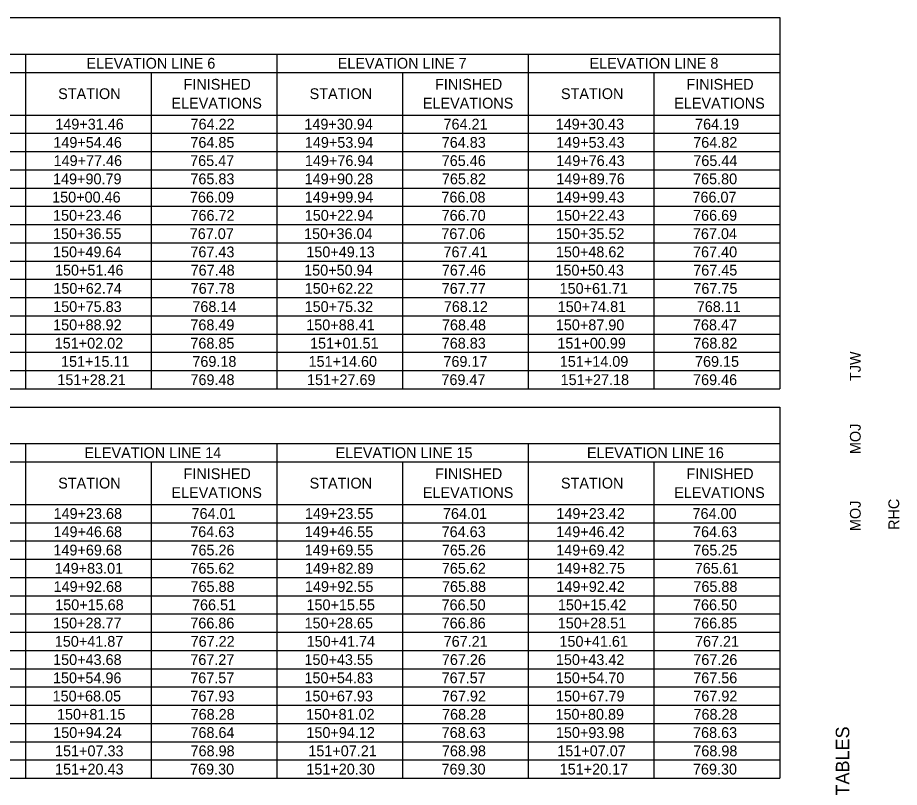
# Model space of a CAD drawing. Extents: x 2.7 to 33.4, y 1.1 to 21.
# Drawn here: x 21.94 to 33.41, y 11 to 21 of the extents above; entities that cross this region are included whole.
import ezdxf

# ---------------------------------------------------------------- set-up
doc = ezdxf.new("R2010")
doc.units = 0
doc.layers.add('BR_X_Beam_Object', color=7, linetype='Continuous')
doc.layers.add('BR_X_Slab_Object', color=7, linetype='Continuous')

msp = doc.modelspace()

# ---------------------------------------------------------------- linework, layer by layer
at = {"layer": 'BR_X_Slab_Object'}
for p, q in [((12.243, 21), (22.046, 21)), ((22.046, 21), (28.582, 21)), ((28.582, 21), (31.85, 21)), ((31.85, 21), (31.85, 19.735)), ((12.243, 20.526), (22.046, 20.526)), ((22.046, 20.526), (28.582, 20.526)), ((22.046, 20.526), (22.046, 19.735)), ((25.314, 20.526), (25.314, 19.735)), ((28.582, 20.526), (31.85, 20.526)), ((28.582, 20.526), (28.582, 19.735)), ((12.243, 20.288), (22.046, 20.288)), ((22.046, 20.288), (28.582, 20.288)), ((23.68, 20.288), (23.68, 19.735)), ((26.948, 20.288), (26.948, 19.735)), ((28.582, 20.288), (31.85, 20.288)), ((30.216, 20.288), (30.216, 19.735)), ((12.243, 19.735), (22.046, 19.735)), ((22.046, 19.735), (28.582, 19.735)), ((22.046, 19.735), (22.046, 18.549)), ((23.68, 19.735), (23.68, 18.549)), ((25.314, 19.735), (25.314, 18.549)), ((26.948, 19.735), (26.948, 18.549)), ((28.582, 19.735), (31.85, 19.735)), ((28.582, 19.735), (28.582, 18.549)), ((30.216, 19.735), (30.216, 18.549)), ((31.85, 19.735), (31.85, 18.549)), ((12.243, 19.498), (22.046, 19.498)), ((22.046, 19.498), (28.582, 19.498)), ((28.582, 19.498), (31.85, 19.498)), ((12.243, 19.261), (22.046, 19.261)), ((22.046, 19.261), (28.582, 19.261)), ((28.582, 19.261), (31.85, 19.261)), ((12.243, 19.024), (22.046, 19.024)), ((22.046, 19.024), (28.582, 19.024)), ((28.582, 19.024), (31.85, 19.024)), ((12.243, 18.786), (22.046, 18.786)), ((22.046, 18.786), (28.582, 18.786)), ((28.582, 18.786), (31.85, 18.786)), ((12.243, 18.549), (22.046, 18.549)), ((22.046, 18.549), (28.582, 18.549)), ((22.046, 18.549), (22.046, 18.312)), ((23.68, 18.549), (23.68, 18.312)), ((25.314, 18.549), (25.314, 18.312)), ((26.948, 18.549), (26.948, 18.312)), ((28.582, 18.549), (31.85, 18.549)), ((28.582, 18.549), (28.582, 18.312)), ((30.216, 18.549), (30.216, 18.312)), ((31.85, 18.549), (31.85, 18.312)), ((12.243, 18.312), (22.046, 18.312)), ((22.046, 18.312), (28.582, 18.312)), ((22.046, 18.312), (22.046, 17.6)), ((23.68, 18.312), (23.68, 17.6)), ((25.314, 18.312), (25.314, 17.6)), ((26.948, 18.312), (26.948, 17.6)), ((28.582, 18.312), (31.85, 18.312)), ((28.582, 18.312), (28.582, 17.6)), ((30.216, 18.312), (30.216, 17.6)), ((31.85, 18.312), (31.85, 17.6)), ((12.243, 18.075), (22.046, 18.075)), ((22.046, 18.075), (28.582, 18.075)), ((28.582, 18.075), (31.85, 18.075)), ((12.243, 17.838), (22.046, 17.838)), ((22.046, 17.838), (28.582, 17.838)), ((28.582, 17.838), (31.85, 17.838)), ((12.243, 17.6), (22.046, 17.6)), ((22.046, 17.6), (28.582, 17.6)), ((22.046, 17.6), (22.046, 17.126)), ((23.68, 17.6), (23.68, 17.126)), ((25.314, 17.6), (25.314, 17.126)), ((26.948, 17.6), (26.948, 17.126)), ((28.582, 17.6), (31.85, 17.6)), ((28.582, 17.6), (28.582, 17.126)), ((30.216, 17.6), (30.216, 17.126)), ((31.85, 17.6), (31.85, 17.126)), ((12.243, 17.363), (22.046, 17.363)), ((22.046, 17.363), (28.582, 17.363)), ((28.582, 17.363), (31.85, 17.363)), ((12.243, 17.126), (22.046, 17.126)), ((22.046, 17.126), (28.582, 17.126)), ((22.046, 17.126), (22.046, 16.415)), ((23.68, 17.126), (23.68, 16.415)), ((25.314, 17.126), (25.314, 16.415)), ((26.948, 17.126), (26.948, 16.415)), ((28.582, 17.126), (31.85, 17.126)), ((28.582, 17.126), (28.582, 16.415)), ((30.216, 17.126), (30.216, 16.415)), ((31.85, 17.126), (31.85, 16.415)), ((12.243, 16.889), (22.046, 16.889)), ((22.046, 16.889), (28.582, 16.889)), ((28.582, 16.889), (31.85, 16.889)), ((12.243, 16.652), (22.046, 16.652)), ((22.046, 16.652), (28.582, 16.652)), ((28.582, 16.652), (31.85, 16.652)), ((12.243, 16.415), (22.046, 16.415)), ((22.046, 16.415), (28.582, 16.415)), ((22.046, 16.415), (22.046, 16.177)), ((23.68, 16.415), (23.68, 16.177)), ((25.314, 16.415), (25.314, 16.177)), ((26.948, 16.415), (26.948, 16.177)), ((28.582, 16.415), (31.85, 16.415)), ((28.582, 16.415), (28.582, 16.177)), ((30.216, 16.415), (30.216, 16.177)), ((31.85, 16.415), (31.85, 16.177)), ((12.243, 16.177), (22.046, 16.177)), ((22.046, 16.177), (28.582, 16.177)), ((28.582, 16.177), (31.85, 16.177)), ((12.243, 15.94), (22.046, 15.94)), ((22.046, 15.94), (28.582, 15.94)), ((28.582, 15.94), (31.85, 15.94)), ((31.85, 15.94), (31.85, 14.952)), ((12.243, 15.466), (22.046, 15.466)), ((22.046, 15.466), (28.582, 15.466)), ((22.046, 15.466), (22.046, 14.952)), ((25.314, 15.466), (25.314, 14.952)), ((28.582, 15.466), (31.85, 15.466)), ((28.582, 15.466), (28.582, 14.952)), ((12.243, 15.229), (22.046, 15.229)), ((22.046, 15.229), (28.582, 15.229)), ((23.68, 15.229), (23.68, 14.952)), ((26.948, 15.229), (26.948, 14.952)), ((28.582, 15.229), (31.85, 15.229)), ((30.216, 15.229), (30.216, 14.952)), ((22.046, 14.952), (22.046, 14.201)), ((23.68, 14.952), (23.68, 14.201)), ((25.314, 14.952), (25.314, 14.201)), ((26.948, 14.952), (26.948, 14.201)), ((28.582, 14.952), (28.582, 14.201)), ((30.216, 14.952), (30.216, 14.201)), ((31.85, 14.952), (31.85, 14.201)), ((12.243, 14.675), (22.046, 14.675)), ((22.046, 14.675), (28.582, 14.675)), ((28.582, 14.675), (31.85, 14.675)), ((12.243, 14.438), (22.046, 14.438)), ((22.046, 14.438), (28.582, 14.438)), ((28.582, 14.438), (31.85, 14.438)), ((12.243, 14.201), (22.046, 14.201)), ((22.046, 14.201), (28.582, 14.201)), ((22.046, 14.201), (22.046, 13.015)), ((23.68, 14.201), (23.68, 13.015)), ((25.314, 14.201), (25.314, 13.015)), ((26.948, 14.201), (26.948, 13.015)), ((28.582, 14.201), (31.85, 14.201)), ((28.582, 14.201), (28.582, 13.015)), ((30.216, 14.201), (30.216, 13.015)), ((31.85, 14.201), (31.85, 13.015)), ((12.243, 13.964), (22.046, 13.964)), ((22.046, 13.964), (28.582, 13.964)), ((28.582, 13.964), (31.85, 13.964)), ((12.243, 13.727), (22.046, 13.727)), ((22.046, 13.727), (28.582, 13.727)), ((28.582, 13.727), (31.85, 13.727)), ((12.243, 13.489), (22.046, 13.489)), ((22.046, 13.489), (28.582, 13.489)), ((28.582, 13.489), (31.85, 13.489)), ((12.243, 13.252), (22.046, 13.252)), ((22.046, 13.252), (28.582, 13.252)), ((28.582, 13.252), (31.85, 13.252)), ((12.243, 13.015), (22.046, 13.015)), ((22.046, 13.015), (28.582, 13.015)), ((22.046, 13.015), (22.046, 11.829)), ((23.68, 13.015), (23.68, 11.829)), ((25.314, 13.015), (25.314, 11.829)), ((26.948, 13.015), (26.948, 11.829)), ((28.582, 13.015), (31.85, 13.015)), ((28.582, 13.015), (28.582, 11.829)), ((30.216, 13.015), (30.216, 11.829)), ((31.85, 13.015), (31.85, 11.829)), ((12.243, 12.778), (22.046, 12.778)), ((22.046, 12.778), (28.582, 12.778)), ((28.582, 12.778), (31.85, 12.778)), ((12.243, 12.541), (22.046, 12.541)), ((22.046, 12.541), (28.582, 12.541)), ((28.582, 12.541), (31.85, 12.541)), ((12.243, 12.304), (22.046, 12.304)), ((22.046, 12.304), (28.582, 12.304)), ((28.582, 12.304), (31.85, 12.304)), ((12.243, 12.066), (22.046, 12.066)), ((22.046, 12.066), (28.582, 12.066)), ((28.582, 12.066), (31.85, 12.066)), ((12.243, 11.829), (22.046, 11.829)), ((22.046, 11.829), (28.582, 11.829)), ((22.046, 11.829), (22.046, 11.118)), ((23.68, 11.829), (23.68, 11.118)), ((25.314, 11.829), (25.314, 11.118)), ((26.948, 11.829), (26.948, 11.118)), ((28.582, 11.829), (31.85, 11.829)), ((28.582, 11.829), (28.582, 11.118)), ((30.216, 11.829), (30.216, 11.118)), ((31.85, 11.829), (31.85, 11.118)), ((12.243, 11.592), (22.046, 11.592)), ((22.046, 11.592), (28.582, 11.592)), ((28.582, 11.592), (31.85, 11.592)), ((12.243, 11.355), (22.046, 11.355)), ((22.046, 11.355), (28.582, 11.355)), ((28.582, 11.355), (31.85, 11.355)), ((12.243, 11.118), (22.046, 11.118)), ((22.046, 11.118), (28.582, 11.118)), ((28.582, 11.118), (31.85, 11.118))]:
    msp.add_line(p, q, dxfattribs=at)

# ---------------------------------------------------------------- texts
at = {"layer": 'BR_X_Beam_Object'}
for s, p in [('ELEVATION LINE 6', (22.839, 20.337)), ('ELEVATION LINE 7', (26.105, 20.337)), ('ELEVATION LINE 8', (29.378, 20.337)), ('FINISHED', (24.102, 20.064)), ('FINISHED', (27.37, 20.064)), ('FINISHED', (30.637, 20.064)), ('STATION', (22.472, 19.942)), ('STATION', (25.74, 19.942)), ('STATION', (29.007, 19.942)), ('ELEVATIONS', (23.944, 19.819)), ('ELEVATIONS', (27.212, 19.819)), ('ELEVATIONS', (30.48, 19.819)), ('149+31.46', (22.434, 19.546)), ('764.22', (24.192, 19.546)), ('149+30.94', (25.672, 19.546)), ('764.21', (27.48, 19.546)), ('149+30.43', (28.938, 19.546)), ('764.19', (30.75, 19.546)), ('149+54.46', (22.409, 19.309)), ('764.85', (24.19, 19.309)), ('149+53.94', (25.678, 19.309)), ('764.83', (27.457, 19.309)), ('149+53.43', (28.944, 19.309)), ('764.82', (30.726, 19.309)), ('149+77.46', (22.412, 19.072)), ('765.47', (24.187, 19.072)), ('149+76.94', (25.679, 19.072)), ('765.46', (27.457, 19.072)), ('149+76.43', (28.945, 19.072)), ('765.44', (30.727, 19.072)), ('149+90.79', (22.405, 18.835)), ('765.83', (24.19, 18.835)), ('149+90.28', (25.675, 18.835)), ('765.82', (27.459, 18.835)), ('149+89.76', (28.946, 18.835)), ('765.80', (30.724, 18.835)), ('150+00.46', (22.393, 18.598)), ('766.09', (24.184, 18.598)), ('149+99.94', (25.677, 18.598)), ('766.08', (27.453, 18.598)), ('149+99.43', (28.943, 18.598)), ('766.07', (30.716, 18.598)), ('150+23.46', (22.405, 18.361)), ('766.72', (24.191, 18.361)), ('150+22.94', (25.677, 18.361)), ('766.70', (27.456, 18.361)), ('150+22.43', (28.943, 18.361)), ('766.69', (30.724, 18.361)), ('150+36.55', (22.404, 18.123)), ('767.07', (24.182, 18.123)), ('150+36.04', (25.668, 18.123)), ('767.06', (27.452, 18.123)), ('150+35.52', (28.942, 18.123)), ('767.04', (30.722, 18.123)), ('150+49.64', (22.405, 17.886)), ('767.43', (24.19, 17.886)), ('150+49.13', (25.697, 17.886)), ('767.41', (27.48, 17.886)), ('150+48.62', (28.941, 17.886)), ('767.40', (30.724, 17.886)), ('150+51.46', (22.43, 17.649)), ('767.48', (24.193, 17.649)), ('150+50.94', (25.669, 17.649)), ('767.46', (27.458, 17.649)), ('150+50.43', (28.935, 17.649)), ('767.45', (30.726, 17.649)), ('150+62.74', (22.409, 17.412)), ('767.78', (24.194, 17.412)), ('150+62.22', (25.676, 17.412)), ('767.77', (27.457, 17.412)), ('150+61.71', (28.989, 17.412)), ('767.75', (30.728, 17.412)), ('150+75.83', (22.407, 17.175)), ('768.14', (24.216, 17.175)), ('150+75.32', (25.675, 17.175)), ('768.12', (27.484, 17.175)), ('150+74.81', (28.964, 17.175)), ('768.11', (30.772, 17.175)), ('150+88.92', (22.406, 16.938)), ('768.49', (24.19, 16.938)), ('150+88.41', (25.696, 16.938)), ('768.48', (27.46, 16.938)), ('150+87.90', (28.94, 16.938)), ('768.47', (30.722, 16.938)), ('151+02.02', (22.427, 16.7)), ('768.85', (24.19, 16.7)), ('151+01.51', (25.746, 16.7)), ('768.83', (27.457, 16.7)), ('151+00.99', (28.96, 16.7)), ('768.82', (30.727, 16.7)), ('151+15.11', (22.509, 16.463)), ('769.18', (24.216, 16.463)), ('151+14.60', (25.726, 16.463)), ('769.17', (27.479, 16.463)), ('151+14.09', (28.992, 16.463)), ('769.15', (30.749, 16.463)), ('151+28.21', (22.461, 16.226)), ('769.48', (24.191, 16.226)), ('151+27.69', (25.706, 16.226)), ('769.47', (27.453, 16.226)), ('151+27.18', (29.002, 16.226)), ('769.46', (30.724, 16.226)), ('ELEVATION LINE 14', (22.812, 15.277)), ('ELEVATION LINE 15', (26.078, 15.277)), ('ELEVATION LINE 16', (29.345, 15.277)), ('FINISHED', (24.102, 15.004)), ('FINISHED', (27.37, 15.004)), ('FINISHED', (30.637, 15.004)), ('STATION', (22.472, 14.882)), ('STATION', (25.74, 14.882)), ('STATION', (29.007, 14.882)), ('ELEVATIONS', (23.944, 14.759)), ('ELEVATIONS', (27.212, 14.759)), ('ELEVATIONS', (30.48, 14.759)), ('149+23.68', (22.412, 14.487)), ('764.01', (24.205, 14.487)), ('149+23.55', (25.679, 14.487)), ('764.01', (27.473, 14.487)), ('149+23.42', (28.947, 14.487)), ('764.00', (30.717, 14.487)), ('149+46.68', (22.411, 14.25)), ('764.63', (24.188, 14.25)), ('149+46.55', (25.677, 14.25)), ('764.63', (27.456, 14.25)), ('149+46.42', (28.945, 14.25)), ('764.63', (30.724, 14.25)), ('149+69.68', (22.41, 14.012)), ('765.26', (24.191, 14.012)), ('149+69.55', (25.677, 14.012)), ('765.26', (27.458, 14.012)), ('149+69.42', (28.945, 14.012)), ('765.25', (30.727, 14.012)), ('149+83.01', (22.426, 13.775)), ('765.62', (24.19, 13.775)), ('149+82.89', (25.68, 13.775)), ('765.62', (27.458, 13.775)), ('149+82.75', (28.948, 13.775)), ('765.61', (30.746, 13.775)), ('149+92.68', (22.412, 13.538)), ('765.88', (24.192, 13.538)), ('149+92.55', (25.679, 13.538)), ('765.88', (27.46, 13.538)), ('149+92.42', (28.947, 13.538)), ('765.88', (30.728, 13.538)), ('150+15.68', (22.433, 13.301)), ('766.51', (24.211, 13.301)), ('150+15.55', (25.699, 13.301)), ('766.50', (27.455, 13.301)), ('150+15.42', (28.967, 13.301)), ('766.50', (30.723, 13.301)), ('150+28.77', (22.405, 13.064)), ('766.86', (24.189, 13.064)), ('150+28.65', (25.674, 13.064)), ('766.86', (27.456, 13.064)), ('150+28.51', (28.965, 13.064)), ('766.85', (30.725, 13.064)), ('150+41.87', (22.428, 12.826)), ('767.22', (24.193, 12.826)), ('150+41.74', (25.701, 12.826)), ('767.21', (27.482, 12.826)), ('150+41.61', (28.987, 12.826)), ('767.21', (30.749, 12.826)), ('150+43.68', (22.406, 12.589)), ('767.27', (24.189, 12.589)), ('150+43.55', (25.673, 12.589)), ('767.26', (27.459, 12.589)), ('150+43.42', (28.941, 12.589)), ('767.26', (30.727, 12.589)), ('150+54.96', (22.404, 12.352)), ('767.57', (24.188, 12.352)), ('150+54.83', (25.673, 12.352)), ('767.57', (27.456, 12.352)), ('150+54.70', (28.94, 12.352)), ('767.56', (30.726, 12.352)), ('150+68.05', (22.399, 12.115)), ('767.93', (24.19, 12.115)), ('150+67.93', (25.673, 12.115)), ('767.92', (27.459, 12.115)), ('150+67.79', (28.943, 12.115)), ('767.92', (30.727, 12.115)), ('150+81.15', (22.456, 11.878)), ('768.28', (24.193, 11.878)), ('150+81.02', (25.694, 11.878)), ('768.28', (27.461, 11.878)), ('150+80.89', (28.936, 11.878)), ('768.28', (30.729, 11.878)), ('150+94.24', (22.407, 11.641)), ('768.64', (24.191, 11.641)), ('150+94.12', (25.698, 11.641)), ('768.63', (27.456, 11.641)), ('150+93.98', (28.941, 11.641)), ('768.63', (30.724, 11.641)), ('151+07.33', (22.431, 11.403)), ('768.98', (24.192, 11.403)), ('151+07.21', (25.723, 11.403)), ('768.98', (27.459, 11.403)), ('151+07.07', (28.959, 11.403)), ('768.98', (30.727, 11.403)), ('151+20.43', (22.431, 11.166)), ('769.30', (24.186, 11.166)), ('151+20.30', (25.697, 11.166)), ('769.30', (27.454, 11.166)), ('151+20.17', (28.99, 11.166)), ('769.30', (30.722, 11.166))]:
    msp.add_text(s, height=0.14, dxfattribs=at).set_placement(p)
at = {"layer": 'BR_X_Slab_Object'}
for s, height, p in [('TJW', 0.14, (32.903, 16.278)), ('MOJ', 0.14, (32.903, 15.329)), ('MOJ', 0.14, (32.903, 14.329)), ('RHC', 0.14, (33.403, 14.344)), ('FINAL DECK SURFACE ELEVATION TABLES', 0.175, (32.754, 6.888))]:
    msp.add_text(s, height=height, rotation=90, dxfattribs=at).set_placement(p)

doc.saveas('drawing.dxf')
